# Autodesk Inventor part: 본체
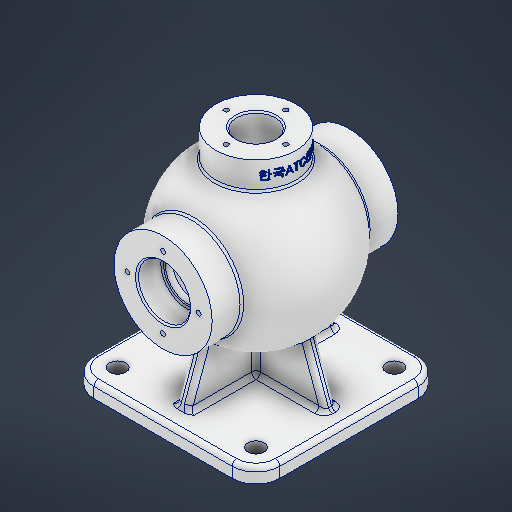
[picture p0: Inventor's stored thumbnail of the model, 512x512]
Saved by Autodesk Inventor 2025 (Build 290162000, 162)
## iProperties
Created: 2025-08
Part Number: 본체
Material: 알루미늄 6061
Document SubType Name: Modeling
Designer: infra023
Density: 2.7 g/cm^3
Appearance: 알루미늄 - 평지
Mass: 2028.23 g
Surface Area: 1139.74 cm^2
Volume: 751.195 cm^3
Author: infra023
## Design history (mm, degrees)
sketch "스케치1"
  geometry: L1 (-62.5, 62.5)-(62.5, 62.5); L2 (62.5, 62.5)-(62.5, -62.5); L3 (62.5, -62.5)-(-62.5, -62.5); L4 (-62.5, -62.5)-(-62.5, 62.5); L5 (-62.5, 62.5)-(62.5, -62.5); L6 (62.5, 62.5)-(-62.5, -62.5); 1 further point
  constraints: 12 end point, 2 midpoint, 2 parallel, 1 horizontal, 1 perpendicular
  dimensions: "d0" = 125 distance of L2.end L3.end; "d1" = 125 distance of L1.end L2.end
extrude "돌출1" new body sketch "스케치1" distance "d2" = 10; taper "d3" = 0 deg
sketch "스케치2"
  geometry: L1 (0, 62.5)-(0, -62.5) reference; L2 (10, 62.5)-(10, -62.5) reference; L3 (0, 62.5)-(0, -62.5) reference; L4 (0, -62.5)-(10, -62.5) reference; L5 (10, 62.5)-(10, -62.5) reference; L6 (0, 62.5)-(10, 62.5) reference; L7 (85, 54)-(85, -54); A1 r 54 centre (85, 0) between (85, 54) and (85, -54); 3 further points
  constraints: 2 end point, 2 midpoint, 2 point on circle, 1 centre point, 1 coincident, 1 horizontal alignment, 1 vertical
  dimensions: "d6" = 108 diameter of A1; "d7" = 85 distance from line of L1 A1.centre
revolve "회전1" sketch "스케치2" stored, may be unused: angle "d8" = 90 deg
node "작업 평면2"
sketch "스케치5"
  geometry: C1 r 33 at (0, 85); C2 r 54 at (0, 85) reference; 1 further point
  constraints: 1 centre point, 1 coincident
  dimensions: "d14" = 66 diameter of C1
extrude "돌출3" join sketch "스케치5" stored distance "d15" = 10; taper "d16" = 0 deg
sketch "스케치6"
  geometry: L1 (62.5, 10)-(-62.5, 10) reference; L2 (-50.5, 10)-(-37.385, 46.034); L3 (-62.5, 0)-(-62.5, 10) reference; L4 (-50.5, 10)-(0, 10); L5 (-37.385, 46.034)-(0, 46.034); L6 (0, 46.034)-(0, 10); 3 further points
  constraints: 8 end point, 1 horizontal, 1 midpoint, 1 perpendicular, 1 point on line, 2 other
  dimensions: "d17" = 12 distance of L1.end L2.start; "d18" = 20 deg angle of L3 L2
extrude "돌출4" join sketch "스케치6" stored distance "d19" = 8; taper "d20" = 0 deg
sketch "스케치8"
  geometry: L1 (-62.5, 10)-(62.5, 10) reference; L2 (50.5, 10)-(37.385, 46.034); L3 (62.5, 10)-(62.5, 30); L4 (37.385, 46.034)-(0, 46.034); L5 (0, 10)-(0, 31) reference; L6 (0, 46.034)-(0, 10); A1 r 54 centre (0, 85) between (37.385, 46.034) and (0, 31) reference; 1 further point
  constraints: 8 end point, 1 collinear, 1 horizontal, 1 point on circle, 1 point on line, 1 vertical
  dimensions: "d26" = 12 distance of L1.end L2.start; "d27" = 20 deg angle of L3 L2
extrude "돌출6" join sketch "스케치8" stored distance "d28" = 8; taper "d29" = 0 deg
sketch "스케치9"
  geometry: L1 (10, -62.5)-(10, 62.5) reference; L2 (10, -50.5)-(46.034, -37.385); L3 (0, -62.5)-(10, -62.5) reference; L4 (46.034, -4)-(46.034, 0) reference; L5 (46.034, -37.385)-(46.034, 0); L6 (46.034, 0)-(10, 0); A1 r 54 centre (85, 0) between (52, 42.743) and (118, 42.743) reference; 2 further points
  constraints: 6 end point, 1 midpoint, 1 point on circle, 1 point on line
  dimensions: "d30" = 12 distance of L1.start L2.start; "d31" = 20 deg angle of L3 L2
extrude "돌출7" join sketch "스케치9" stored distance "d32" = 8; taper "d33" = 0 deg
node "작업 평면3"
sketch "스케치10"
  geometry: C1 r 27 at (0, 0); 1 further point
  constraints: 1 centre point, 1 coincident
  dimensions: "d35" = 54 diameter of C1
extrude "돌출8" join sketch "스케치10" stored distance "d36" = 8; taper "d37" = 0 deg
sketch "스케치11"
  geometry: 1 further point
sketch "스케치12"
  geometry: L1 (-27, 131.765)-(27, 131.765) reference; L2 (0, 31)-(0, 46.034) reference; L3 (0, 31)-(0, 46.034) reference; L4 (-44, 85)-(44, 85); C1 r 44 at (0, 85); C2 r 44 at (0, 85); A1 r 54 centre (0, 85) between (-37.385, 46.034) and (0, 31) reference; A2 r 54 centre (0, 85) between (0, 31) and (37.385, 46.034) reference; A3 r 44 centre (0, 85) between (-44, 85) and (44, 85); 4 further points
  constraints: 3 centre point, 3 coincident, 3 concentric, 2 end point, 2 point on circle, 1 horizontal, 1 midpoint
  dimensions: "d98" = 88 diameter of C1; "d99" = 44 distance from line of point (44, 85) L2; "d100" = 46.76537 distance from line of point (44, 85) L1; "d101" = 44 distance from line of point (-44, 85) L2; "d102" = 46.76537 distance from line of point (-44, 85) L1
revolve "회전2" sketch "스케치12" stored, may be unused: angle "d38" = 90 deg
sketch "스케치13"
  geometry: 1 further point
hole "구멍1" sketch "스케치13" at (0, 0) diameter "d39" = 26; stored, may be unused: countersink angle "d43" = 90 deg, drill point angle "d45" = 118 deg; dims "d40" = 6, "d41" = 4, "d42" = 2, "d44" = 8
sketch "스케치14"
  geometry: C1 r 33 at (0, 0) reference; 1 further point
  node "투영된 루프3"
hole "구멍2" sketch "스케치14" diameter "d46" = 30; stored, may be unused: countersink angle "d50" = 90 deg, drill point angle "d52" = 118 deg; dims "d47" = 6, "d48" = 35, "d49" = 16, "d51" = 8
sketch "스케치15"
  geometry: L1 (0, 24)-(0, -24); L2 (-24, 0)-(24, 0); C1 r 17.5 at (0, 0) reference; C2 r 33 at (0, 0) reference; A1 r 24 centre (0, 0) between (0, 24) and (0, -24); 3 further points
  constraints: 4 end point, 4 point on circle, 3 coincident, 2 midpoint, 1 centre point, 1 horizontal, 1 vertical
  dimensions: "d53" = 48 diameter of A1
hole "구멍3" sketch "스케치15" at (0, 24), (-24, 0), (0, -24), (24, 0) diameter "d54" = 3.242; stored, may be unused: countersink angle "d58" = 90 deg, drill point angle "d60" = 118 deg; dims "d55" = 12, "d56" = 4, "d57" = 2, "d59" = 15
sketch "스케치16"
  geometry: L1 (-46.5, 46.5)-(46.5, 46.5); L2 (46.5, 46.5)-(46.5, -46.5); L3 (46.5, -46.5)-(-46.5, -46.5); L4 (-46.5, -46.5)-(-46.5, 46.5); L5 (-46.5, 46.5)-(46.5, -46.5); L6 (46.5, 46.5)-(-46.5, -46.5); 1 further point
  constraints: 12 end point, 2 midpoint, 2 parallel, 1 horizontal, 1 perpendicular
  dimensions: "d61" = 93 distance of L2.end L3.end; "d62" = 93 distance of L1.end L2.end
hole "구멍4" sketch "스케치16" at (-46.5, 46.5), (46.5, 46.5), (-46.5, -46.5), (46.5, -46.5) diameter "d63" = 11; stored, may be unused: countersink angle "d67" = 90 deg, drill point angle "d69" = 118 deg; dims "d64" = 12, "d65" = 4, "d66" = 2, "d68" = 8
sketch "스케치17"
  geometry: L1 (-37.385, 0)-(0, 0) reference; L2 (0, 20)-(0, -20); L3 (-20, 0)-(20, 0); A1 r 20 centre (0, 0) between (0, 20) and (0, -20); 2 further points
  constraints: 4 end point, 4 point on circle, 2 coincident, 2 midpoint, 2 point on line, 1 centre point, 1 vertical
  dimensions: "d70" = 40 diameter of A1
hole "구멍5" sketch "스케치17" at (0, 20), (-20, 0), (0, -20), (20, 0) diameter "d71" = 3.242; stored, may be unused: countersink angle "d75" = 90 deg, drill point angle "d77" = 118 deg; dims "d72" = 9, "d73" = 4, "d74" = 2, "d76" = 11
fillet "모깎기1" dims "d78" = 16
fillet "모깎기2" dims "d79" = 3
fillet "모깎기3" dims "d80" = 3
chamfer "모따기1" distance "d81" = 1; stored, may be unused: second distance "d82" = 2, angle "d83" = 45 deg
chamfer "모따기2" distance "d84" = 1; stored, may be unused: second distance "d85" = 2, angle "d86" = 45 deg
chamfer "모따기3" distance "d87" = 0.6; stored, may be unused: second distance "d88" = 2, angle "d89" = 45 deg
chamfer "모따기4" distance "d90" = 1; stored, may be unused: second distance "d91" = 2, angle "d92" = 45 deg
node "작업 평면4"
sketch "스케치18"
  geometry: L1 (150, 16.406)-(150, -17); L2 (150, -17)-(132, -17); L3 (132, -17)-(132, 16.406); L4 (132, 16.406)-(150, 16.406); L5 (150, -27)-(150, 27) reference; L6 (132.765, 27)-(132.765, -27) reference; 4 further points
  constraints: 3 midpoint, 1 vertical alignment, 2 other
  dimensions: "d94" = 9 horizontal distance of L5.end point (141, 16.406)
feature "엠보싱1" sketch "스케치18" dims "d0" = 125, "d1" = 125, "d95" = 0.5, "d96" = 0
node "솔리드1"
mirror "미러2"
mirror "미러3"
mirror "미러4"
node "투영된 루프1"
node "투영된 루프2"
node "투영된 루프4"
node "투영된 루프5"
feature "A9D066F2-1C7D-4E18-AEED-F7BC21143FA4" dims "d63" = 11, "d64" = 12, "d65" = 4, "d66" = 2, "d67" = 90 deg, "d68" = 8, "d69" = 118 deg
other parameters: "d13" = 62.5, "d93" = 27
